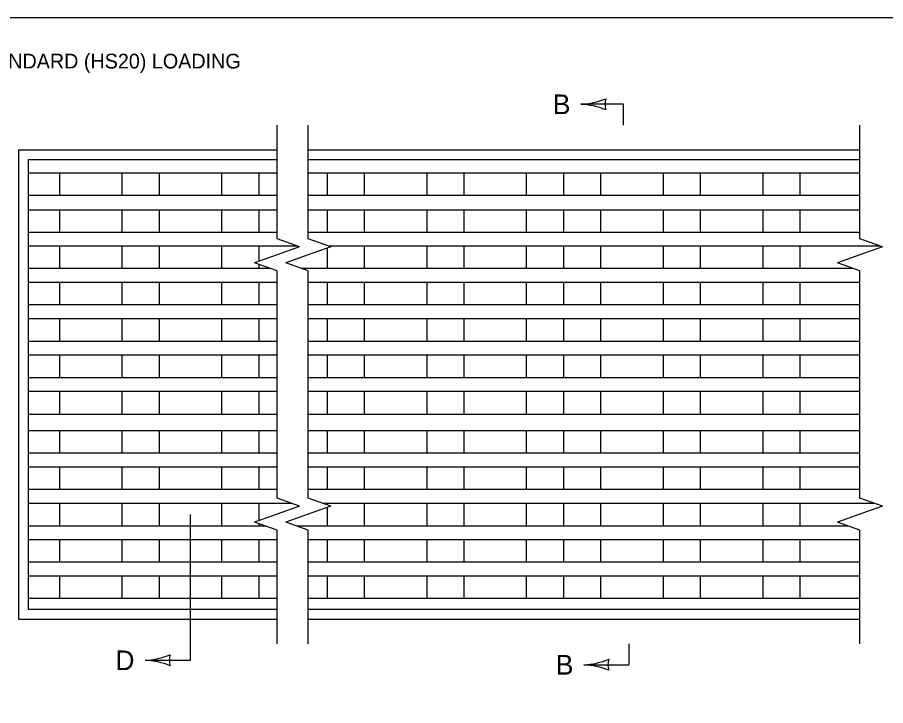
# Model space of a CAD drawing. Extents: x 49991.4 to 50021, y 49987.6 to 50011.4.
# Drawn here: x 50010.101 to 50013.631, y 49996.201 to 49998.999 of the extents above; entities that cross this region are included whole.
import ezdxf

# ---------------------------------------------------------------- set-up
doc = ezdxf.new("R2010")
doc.units = 0
for name, color, linetype in [('Level 1', 7, 'Continuous'), ('Level 2', 7, 'Continuous'), ('Level 6', 7, 'Continuous')]:
    doc.layers.add(name, color=color, linetype=linetype)

msp = doc.modelspace()

# ---------------------------------------------------------------- linework, layer by layer
at = {"layer": 'Level 1'}
for p, q in [((50010.1054, 49998.4611), (50010.1054, 49996.5523)), ((50010.1054, 49998.4611), (50011.1574, 49998.4611)), ((50011.2838, 49998.4611), (50013.5267, 49998.4611)), ((50010.1454, 49998.4211), (50010.1454, 49996.5923)), ((50010.1454, 49998.4211), (50011.1574, 49998.4211)), ((50011.2846, 49998.4211), (50013.525, 49998.4211)), ((50011.1574, 49998.3652), (50010.1454, 49998.3652)), ((50010.2724, 49998.3652), (50010.2724, 49998.2744)), ((50010.5266, 49998.3652), (50010.5266, 49998.2744)), ((50010.6776, 49998.3652), (50010.6776, 49998.2744)), ((50010.9318, 49998.3652), (50010.9318, 49998.2744)), ((50011.0827, 49998.3652), (50011.0827, 49998.2744)), ((50013.5267, 49998.3652), (50011.2846, 49998.3652)), ((50011.3601, 49998.3652), (50011.3601, 49998.2744)), ((50011.5112, 49998.3652), (50011.5112, 49998.2744)), ((50011.7654, 49998.3652), (50011.7654, 49998.2744)), ((50011.9162, 49998.3652), (50011.9162, 49998.2744)), ((50012.1704, 49998.3652), (50012.1704, 49998.2744)), ((50012.3212, 49998.3652), (50012.3212, 49998.2744)), ((50012.472, 49998.3652), (50012.472, 49998.2744)), ((50012.7262, 49998.3652), (50012.7262, 49998.2744)), ((50012.8773, 49998.3652), (50012.8773, 49998.2744)), ((50013.1315, 49998.3652), (50013.1315, 49998.2744)), ((50013.2823, 49998.3652), (50013.2823, 49998.2744)), ((50011.1574, 49998.2744), (50010.1454, 49998.2744)), ((50013.5252, 49998.2744), (50011.2846, 49998.2744)), ((50010.1454, 49998.2165), (50011.1574, 49998.2165)), ((50010.2724, 49998.2165), (50010.2724, 49998.1264)), ((50010.5266, 49998.2165), (50010.5266, 49998.1264)), ((50010.6776, 49998.2165), (50010.6776, 49998.1264)), ((50010.9318, 49998.2165), (50010.9318, 49998.1264)), ((50011.0827, 49998.2165), (50011.0827, 49998.1264)), ((50011.2846, 49998.2165), (50013.5253, 49998.2165)), ((50011.3601, 49998.2165), (50011.3601, 49998.1264)), ((50011.5112, 49998.2165), (50011.5112, 49998.1264)), ((50011.7654, 49998.2165), (50011.7654, 49998.1264)), ((50011.9162, 49998.2165), (50011.9162, 49998.1264)), ((50012.1704, 49998.2165), (50012.1704, 49998.1264)), ((50012.3212, 49998.2165), (50012.3212, 49998.1264)), ((50012.472, 49998.2165), (50012.472, 49998.1264)), ((50012.7262, 49998.2165), (50012.7262, 49998.1264)), ((50012.8773, 49998.2165), (50012.8773, 49998.1264)), ((50013.1315, 49998.2165), (50013.1315, 49998.1264)), ((50013.2823, 49998.2165), (50013.2823, 49998.1264)), ((50010.1454, 49998.1264), (50011.1574, 49998.1264)), ((50011.2846, 49998.1264), (50013.5267, 49998.1264)), ((50010.1454, 49998.0696), (50011.2395, 49998.0696)), ((50010.2724, 49998.0696), (50010.2724, 49997.9788)), ((50010.5266, 49998.0696), (50010.5266, 49997.9788)), ((50010.6776, 49998.0696), (50010.6776, 49997.9788)), ((50010.9318, 49998.0696), (50010.9318, 49997.9788)), ((50011.0827, 49998.0696), (50011.0827, 49998.0074)), ((50011.3601, 49998.0609), (50011.3601, 49997.9788)), ((50011.3659, 49998.0696), (50013.6088, 49998.0696)), ((50011.5112, 49998.0696), (50011.5112, 49997.9788)), ((50011.7654, 49998.0696), (50011.7654, 49997.9788)), ((50011.9162, 49998.0696), (50011.9162, 49997.9788)), ((50012.1704, 49998.0696), (50012.1704, 49997.9788)), ((50012.3212, 49998.0696), (50012.3212, 49997.9788)), ((50012.472, 49998.0696), (50012.472, 49997.9788)), ((50012.7262, 49998.0696), (50012.7262, 49997.9788)), ((50012.8773, 49998.0696), (50012.8773, 49997.9788)), ((50013.1315, 49998.0696), (50013.1315, 49997.9788)), ((50013.2823, 49998.0696), (50013.2823, 49997.9788)), ((50011.0827, 49997.9956), (50011.0827, 49997.9788)), ((50010.1454, 49997.9788), (50011.13, 49997.9788)), ((50011.2564, 49997.9788), (50013.4993, 49997.9788)), ((50010.1454, 49997.9219), (50011.1574, 49997.9219)), ((50010.5266, 49997.9219), (50010.5266, 49997.831)), ((50010.6776, 49997.9219), (50010.6776, 49997.831)), ((50010.9318, 49997.9219), (50010.9318, 49997.831)), ((50011.0827, 49997.9219), (50011.0827, 49997.831)), ((50011.2838, 49997.9219), (50013.5253, 49997.9219)), ((50011.3601, 49997.9219), (50011.3601, 49997.831)), ((50011.5112, 49997.9219), (50011.5112, 49997.831)), ((50011.7654, 49997.9219), (50011.7654, 49997.831)), ((50011.9162, 49997.9219), (50011.9162, 49997.831)), ((50012.1704, 49997.9219), (50012.1704, 49997.831)), ((50012.3212, 49997.9219), (50012.3212, 49997.831)), ((50012.472, 49997.9219), (50012.472, 49997.831)), ((50012.7262, 49997.9219), (50012.7262, 49997.831)), ((50012.8773, 49997.9219), (50012.8773, 49997.831)), ((50013.1315, 49997.9219), (50013.1315, 49997.831)), ((50013.2823, 49997.9219), (50013.2823, 49997.831)), ((50010.1454, 49997.831), (50011.1574, 49997.831)), ((50010.6776, 49997.831), (50010.6776, 49997.831)), ((50011.2838, 49997.831), (50013.5258, 49997.831)), ((50010.1454, 49997.7742), (50011.1574, 49997.7742)), ((50010.5266, 49997.7742), (50010.5266, 49997.6832)), ((50010.6776, 49997.7742), (50010.6776, 49997.6832)), ((50010.9318, 49997.7742), (50010.9318, 49997.6832)), ((50011.0827, 49997.7742), (50011.0827, 49997.6832)), ((50011.2838, 49997.7742), (50013.526, 49997.7742)), ((50011.3601, 49997.7742), (50011.3601, 49997.6832)), ((50011.5112, 49997.7742), (50011.5112, 49997.6832)), ((50011.7654, 49997.7742), (50011.7654, 49997.6832)), ((50011.9162, 49997.7742), (50011.9162, 49997.6832)), ((50012.1704, 49997.7742), (50012.1704, 49997.6832)), ((50012.3212, 49997.7742), (50012.3212, 49997.6832)), ((50012.472, 49997.7742), (50012.472, 49997.6832)), ((50012.7262, 49997.7742), (50012.7262, 49997.6832)), ((50012.8773, 49997.7742), (50012.8773, 49997.6832)), ((50013.1315, 49997.7742), (50013.1315, 49997.6832)), ((50013.2823, 49997.7742), (50013.2823, 49997.6832)), ((50010.1454, 49997.6832), (50011.1574, 49997.6832)), ((50011.2838, 49997.6832), (50013.5264, 49997.6832)), ((50010.1454, 49997.6265), (50011.1574, 49997.6265)), ((50010.5266, 49997.6265), (50010.5266, 49997.5355)), ((50010.6776, 49997.6265), (50010.6776, 49997.5355)), ((50010.9318, 49997.6265), (50010.9318, 49997.5355)), ((50011.0827, 49997.6265), (50011.0827, 49997.5355)), ((50011.2838, 49997.6265), (50013.5267, 49997.6265)), ((50011.3601, 49997.6265), (50011.3601, 49997.5355)), ((50011.5112, 49997.6265), (50011.5112, 49997.5355)), ((50011.7654, 49997.6265), (50011.7654, 49997.5355)), ((50011.9162, 49997.6265), (50011.9162, 49997.5355)), ((50012.1704, 49997.6265), (50012.1704, 49997.5355)), ((50012.3212, 49997.6265), (50012.3212, 49997.5355)), ((50012.472, 49997.6265), (50012.472, 49997.5355)), ((50012.7262, 49997.6265), (50012.7262, 49997.5355)), ((50012.8773, 49997.6265), (50012.8773, 49997.5355)), ((50013.1315, 49997.6265), (50013.1315, 49997.5355)), ((50013.2823, 49997.6265), (50013.2823, 49997.5355)), ((50010.1454, 49997.5355), (50011.1574, 49997.5355)), ((50011.2838, 49997.5355), (50013.5267, 49997.5355)), ((50010.1454, 49997.4788), (50011.1574, 49997.4788)), ((50010.5266, 49997.4788), (50010.5266, 49997.3862)), ((50010.6776, 49997.4788), (50010.6776, 49997.3862)), ((50010.9318, 49997.4788), (50010.9318, 49997.3862)), ((50011.0827, 49997.4788), (50011.0827, 49997.3862)), ((50011.2838, 49997.4788), (50013.526, 49997.4788)), ((50011.3601, 49997.4788), (50011.3601, 49997.3862)), ((50011.5112, 49997.4788), (50011.5112, 49997.3862)), ((50011.7654, 49997.4788), (50011.7654, 49997.3862)), ((50011.9162, 49997.4788), (50011.9162, 49997.3862)), ((50012.1704, 49997.4788), (50012.1704, 49997.3862)), ((50012.3212, 49997.4788), (50012.3212, 49997.3862)), ((50012.472, 49997.4788), (50012.472, 49997.3862)), ((50012.7262, 49997.4788), (50012.7262, 49997.3862)), ((50012.8773, 49997.4788), (50012.8773, 49997.3862)), ((50013.1315, 49997.4788), (50013.1315, 49997.3862)), ((50013.2823, 49997.4788), (50013.2823, 49997.3862)), ((50010.1454, 49997.3862), (50011.1574, 49997.3862)), ((50011.2838, 49997.3862), (50013.526, 49997.3862)), ((50010.1466, 49997.3196), (50011.1574, 49997.3196)), ((50010.5266, 49997.3196), (50010.5266, 49997.2287)), ((50010.6776, 49997.3196), (50010.6776, 49997.2287)), ((50010.9318, 49997.3196), (50010.9318, 49997.2287)), ((50011.0827, 49997.3196), (50011.0827, 49997.2287)), ((50011.2838, 49997.3196), (50013.526, 49997.3196)), ((50011.3601, 49997.3196), (50011.3601, 49997.2287)), ((50011.5112, 49997.3196), (50011.5112, 49997.2287)), ((50011.7654, 49997.3196), (50011.7654, 49997.2287)), ((50011.9162, 49997.3196), (50011.9162, 49997.2287)), ((50012.1704, 49997.3196), (50012.1704, 49997.2287)), ((50012.3212, 49997.3196), (50012.3212, 49997.2287)), ((50012.472, 49997.3196), (50012.472, 49997.2287)), ((50012.7262, 49997.3196), (50012.7262, 49997.2287)), ((50012.8773, 49997.3196), (50012.8773, 49997.2287)), ((50013.1315, 49997.3196), (50013.1315, 49997.2287)), ((50013.2823, 49997.3196), (50013.2823, 49997.2287)), ((50010.1454, 49997.2287), (50011.1574, 49997.2287)), ((50011.1086, 49997.2287), (50011.1086, 49997.2286)), ((50011.2838, 49997.2287), (50013.526, 49997.2287)), ((50010.1454, 49997.1719), (50011.1574, 49997.1719)), ((50010.2724, 49997.1719), (50010.2724, 49997.081)), ((50010.5266, 49997.1719), (50010.5266, 49997.081)), ((50010.6776, 49997.1719), (50010.6776, 49997.081)), ((50010.9318, 49997.1719), (50010.9318, 49997.081)), ((50011.0827, 49997.1719), (50011.0827, 49997.081)), ((50011.2838, 49997.1719), (50013.526, 49997.1719)), ((50011.3601, 49997.1719), (50011.3601, 49997.081)), ((50011.5112, 49997.1719), (50011.5112, 49997.081)), ((50011.7654, 49997.1719), (50011.7654, 49997.081)), ((50011.9162, 49997.1719), (50011.9162, 49997.081)), ((50012.1704, 49997.1719), (50012.1704, 49997.081)), ((50012.3212, 49997.1719), (50012.3212, 49997.081)), ((50012.472, 49997.1719), (50012.472, 49997.081)), ((50012.7262, 49997.1719), (50012.7262, 49997.081)), ((50012.8773, 49997.1719), (50012.8773, 49997.081)), ((50013.1315, 49997.1719), (50013.1315, 49997.081)), ((50013.2823, 49997.1719), (50013.2823, 49997.081)), ((50010.1454, 49997.081), (50011.1574, 49997.081)), ((50011.2838, 49997.081), (50013.526, 49997.081)), ((50010.1454, 49997.0242), (50011.2141, 49997.0242)), ((50010.2724, 49997.0242), (50010.2724, 49996.9316)), ((50010.5266, 49997.0242), (50010.5266, 49996.9316)), ((50010.6776, 49997.0242), (50010.6776, 49996.9316)), ((50010.9318, 49997.0242), (50010.9318, 49996.9316)), ((50011.0827, 49997.0242), (50011.0827, 49996.953)), ((50011.3405, 49997.0242), (50013.5834, 49997.0242)), ((50011.3601, 49997.0242), (50011.3601, 49997.0173)), ((50011.3601, 49997.0065), (50011.3601, 49996.9316)), ((50011.5112, 49997.0242), (50011.5112, 49996.9316)), ((50011.7654, 49997.0242), (50011.7654, 49996.9316)), ((50011.9162, 49997.0242), (50011.9162, 49996.9316)), ((50012.1704, 49997.0242), (50012.1704, 49996.9316)), ((50012.3212, 49997.0242), (50012.3212, 49996.9316)), ((50012.472, 49997.0242), (50012.472, 49996.9316)), ((50012.7262, 49997.0242), (50012.7262, 49996.9316)), ((50012.8773, 49997.0242), (50012.8773, 49996.9316)), ((50013.1315, 49997.0242), (50013.1315, 49996.9316)), ((50013.2823, 49997.0242), (50013.2823, 49996.9316)), ((50010.1454, 49996.9316), (50011.1097, 49996.9316)), ((50011.0827, 49996.9412), (50011.0827, 49996.9316)), ((50011.2361, 49996.9316), (50013.479, 49996.9316)), ((50010.1454, 49996.8766), (50011.1574, 49996.8766)), ((50010.2724, 49996.8766), (50010.2724, 49996.7855)), ((50010.5266, 49996.8766), (50010.5266, 49996.7855)), ((50010.6776, 49996.8766), (50010.6776, 49996.7855)), ((50010.9318, 49996.8766), (50010.9318, 49996.7855)), ((50011.0827, 49996.8766), (50011.0827, 49996.7855)), ((50011.2838, 49996.8766), (50013.5267, 49996.8766)), ((50011.3601, 49996.8766), (50011.3601, 49996.7855)), ((50011.5112, 49996.8766), (50011.5112, 49996.7855)), ((50011.7654, 49996.8766), (50011.7654, 49996.7855)), ((50011.9162, 49996.8766), (50011.9162, 49996.7855)), ((50012.1704, 49996.8766), (50012.1704, 49996.7855)), ((50012.3212, 49996.8766), (50012.3212, 49996.7855)), ((50012.472, 49996.8766), (50012.472, 49996.7855)), ((50012.7262, 49996.8766), (50012.7262, 49996.7855)), ((50012.8773, 49996.8766), (50012.8773, 49996.7855)), ((50013.1315, 49996.8766), (50013.1315, 49996.7855)), ((50013.2823, 49996.8766), (50013.2823, 49996.7855)), ((50010.1454, 49996.7855), (50011.1574, 49996.7855)), ((50011.2838, 49996.7855), (50013.5267, 49996.7855)), ((50010.1454, 49996.7279), (50011.1574, 49996.7279)), ((50010.2724, 49996.7279), (50010.2724, 49996.6378)), ((50010.5266, 49996.7279), (50010.5266, 49996.6378)), ((50010.6776, 49996.7279), (50010.6776, 49996.6378)), ((50010.9318, 49996.7279), (50010.9318, 49996.6378)), ((50011.0827, 49996.7279), (50011.0827, 49996.6378)), ((50011.2838, 49996.7279), (50013.5267, 49996.7279)), ((50011.3601, 49996.7279), (50011.3601, 49996.6378)), ((50011.5112, 49996.7279), (50011.5112, 49996.6378)), ((50011.7654, 49996.7279), (50011.7654, 49996.6378)), ((50011.9162, 49996.7279), (50011.9162, 49996.6378)), ((50012.1704, 49996.7279), (50012.1704, 49996.6378)), ((50012.3212, 49996.7279), (50012.3212, 49996.6378)), ((50012.472, 49996.7279), (50012.472, 49996.6378)), ((50012.7262, 49996.7279), (50012.7262, 49996.6378)), ((50012.8773, 49996.7279), (50012.8773, 49996.6378)), ((50013.1315, 49996.7279), (50013.1315, 49996.6378)), ((50013.2823, 49996.7279), (50013.2823, 49996.6378)), ((50010.1454, 49996.6378), (50011.1574, 49996.6378)), ((50011.2838, 49996.6378), (50013.5267, 49996.6378)), ((50010.1454, 49996.5923), (50011.1574, 49996.5923)), ((50011.2838, 49996.5923), (50013.5267, 49996.5923)), ((50010.1054, 49996.5523), (50011.1574, 49996.5523)), ((50011.2838, 49996.5523), (50013.5267, 49996.5523))]:
    msp.add_line(p, q, dxfattribs=at)
msp.add_lwpolyline([(49999.3835, 49998.9992), (50016.7501, 49998.9992), (50016.7501, 49987.7988), (49999.3835, 49987.7988)], close=True, dxfattribs=at)
for points in [[(50010.2724, 49997.9219), (50010.2724, 49997.831)], [(50010.2724, 49997.7742), (50010.2724, 49997.6832)], [(50010.2724, 49997.6265), (50010.2724, 49997.5355)], [(50010.2724, 49997.4788), (50010.2724, 49997.3862)], [(50010.2724, 49997.3196), (50010.2724, 49997.3196), (50010.2724, 49997.2287)]]:
    msp.add_lwpolyline(points, dxfattribs=at)
at = {"layer": 'Level 6'}
for p, q in [((50012.566, 49998.6456), (50012.3924, 49998.6456)), ((50012.566, 49998.5615), (50012.566, 49998.6456)), ((50011.1574, 49998.0987), (50011.1574, 49998.5611)), ((50011.2838, 49998.0987), (50011.2838, 49998.5611)), ((50013.5267, 49998.0987), (50013.5267, 49998.5611)), ((50011.2488, 49998.0663), (50011.1574, 49998.0987)), ((50011.3752, 49998.0663), (50011.2838, 49998.0987)), ((50013.6181, 49998.0663), (50013.5267, 49998.0987)), ((50011.2488, 49998.0663), (50011.1574, 49998.0339)), ((50011.3752, 49998.0663), (50011.2838, 49998.0339)), ((50013.6181, 49998.0663), (50013.5267, 49998.0339)), ((50011.1574, 49998.0339), (50011.066, 49998.0015)), ((50011.2838, 49998.0339), (50011.1924, 49998.0015)), ((50013.5267, 49998.0339), (50013.4353, 49998.0015)), ((50011.1574, 49997.9691), (50011.066, 49998.0015)), ((50011.2838, 49997.9691), (50011.1924, 49998.0015)), ((50013.5267, 49997.9691), (50013.4353, 49998.0015)), ((50011.1574, 49997.0443), (50011.1574, 49997.9691)), ((50011.2838, 49997.0443), (50011.2838, 49997.9691)), ((50013.5267, 49997.0443), (50013.5267, 49997.9691)), ((50011.2488, 49997.0119), (50011.1574, 49997.0443)), ((50011.3752, 49997.0119), (50011.2838, 49997.0443)), ((50013.6181, 49997.0119), (50013.5267, 49997.0443)), ((50011.2488, 49997.0119), (50011.1574, 49996.9795)), ((50011.3752, 49997.0119), (50011.2838, 49996.9795)), ((50013.6181, 49997.0119), (50013.5267, 49996.9795)), ((50010.8047, 49996.3849), (50010.8047, 49996.9782)), ((50011.1574, 49996.9795), (50011.066, 49996.9471)), ((50011.2838, 49996.9795), (50011.1924, 49996.9471)), ((50013.5267, 49996.9795), (50013.4353, 49996.9471)), ((50011.1574, 49996.9147), (50011.066, 49996.9471)), ((50011.2838, 49996.9147), (50011.1924, 49996.9471)), ((50013.5267, 49996.9147), (50013.4353, 49996.9471)), ((50011.1574, 49996.4523), (50011.1574, 49996.9147)), ((50011.2838, 49996.4523), (50011.2838, 49996.9147)), ((50013.5267, 49996.4523), (50013.5267, 49996.9147)), ((50012.5881, 49996.3698), (50012.5881, 49996.4523)), ((50010.6211, 49996.3849), (50010.8047, 49996.3849)), ((50012.4045, 49996.3667), (50012.5881, 49996.3667))]:
    msp.add_line(p, q, dxfattribs=at)
for centre, radius, start, end in [((50012.3771, 49998.9559), 0.3107, 272.8273, 292.0772), ((50012.5634, 49998.6456), 0.073, 162.1388, 197.8612), ((50012.3802, 49998.3494), 0.2964, 67.456, 87.6395), ((50010.6058, 49996.6952), 0.3107, 272.8273, 292.0772), ((50010.7921, 49996.3849), 0.073, 162.1388, 197.8612), ((50010.6089, 49996.0887), 0.2964, 67.456, 87.6395), ((50012.3892, 49996.677), 0.3107, 272.8273, 292.0772), ((50012.3923, 49996.0705), 0.2964, 67.456, 87.6395), ((50012.5755, 49996.3667), 0.073, 162.1388, 197.8612)]:
    msp.add_arc(centre, radius, start, end, dxfattribs=at)

# ---------------------------------------------------------------- texts
at = {"layer": 'Level 2'}
for s, height, p in [('LIVE LOADING: STANDARD (HS20) LOADING', 0.06, (50009.3061, 49998.7913)), ('B', 0.08, (50012.2784, 49998.6056)), ('D', 0.08, (50010.5001, 49996.3449)), ('B', 0.08, (50012.2905, 49996.3267))]:
    msp.add_text(s, height=height, dxfattribs=at).set_placement(p)

doc.saveas('drawing.dxf')
